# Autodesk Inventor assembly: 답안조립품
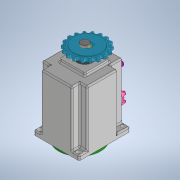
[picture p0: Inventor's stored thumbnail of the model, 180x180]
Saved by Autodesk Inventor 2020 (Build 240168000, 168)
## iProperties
Created: 2022-01
Part Number: 답안조립품
Document SubType Name: Assembly
Designer: user
Author: user
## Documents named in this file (16)
- C:\Users\user\Desktop\720112V1005\답안조립품.iam
- C:\Users\user\Desktop\720112V1005\멈춤나사 M3.ipt
- C:\Users\user\Desktop\720112V1005\메인 축.ipt
- C:\Users\user\Desktop\720112V1005\베어링 608.ipt
- C:\Users\user\Desktop\720112V1005\베어링 6003.ipt
- C:\Users\user\Desktop\720112V1005\본체.ipt
- C:\Users\user\Desktop\720112V1005\볼트 M4 x 10.ipt
- C:\Users\user\Desktop\720112V1005\부시.ipt
- C:\Users\user\Desktop\720112V1005\상부 캡.ipt
- C:\Users\user\Desktop\720112V1005\서브 축.ipt
- C:\Users\user\Desktop\720112V1005\스프로킷.ipt
- C:\Users\user\Desktop\720112V1005\슬라이더.ipt
- C:\Users\user\Desktop\720112V1005\오일 실 8 x 22 x 7.ipt
- C:\Users\user\Desktop\720112V1005\오일 실 17 x 32 x 8.ipt
- C:\Users\user\Desktop\720112V1005\커버.ipt
- C:\Users\user\Desktop\720112V1005\키 5 x 5.ipt
